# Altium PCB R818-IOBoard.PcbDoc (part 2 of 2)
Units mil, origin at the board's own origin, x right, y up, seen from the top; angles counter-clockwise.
Board outline 4330.71 x 4330.71 mil, 4 copper layers (Top Layer, Layer 2, Layer 1, Bottom Layer), stack 33.574 mil thick; 161 components, 167 nets, 792 pads, 698 vias.
Unrouted connection lines stored in the file: 71.
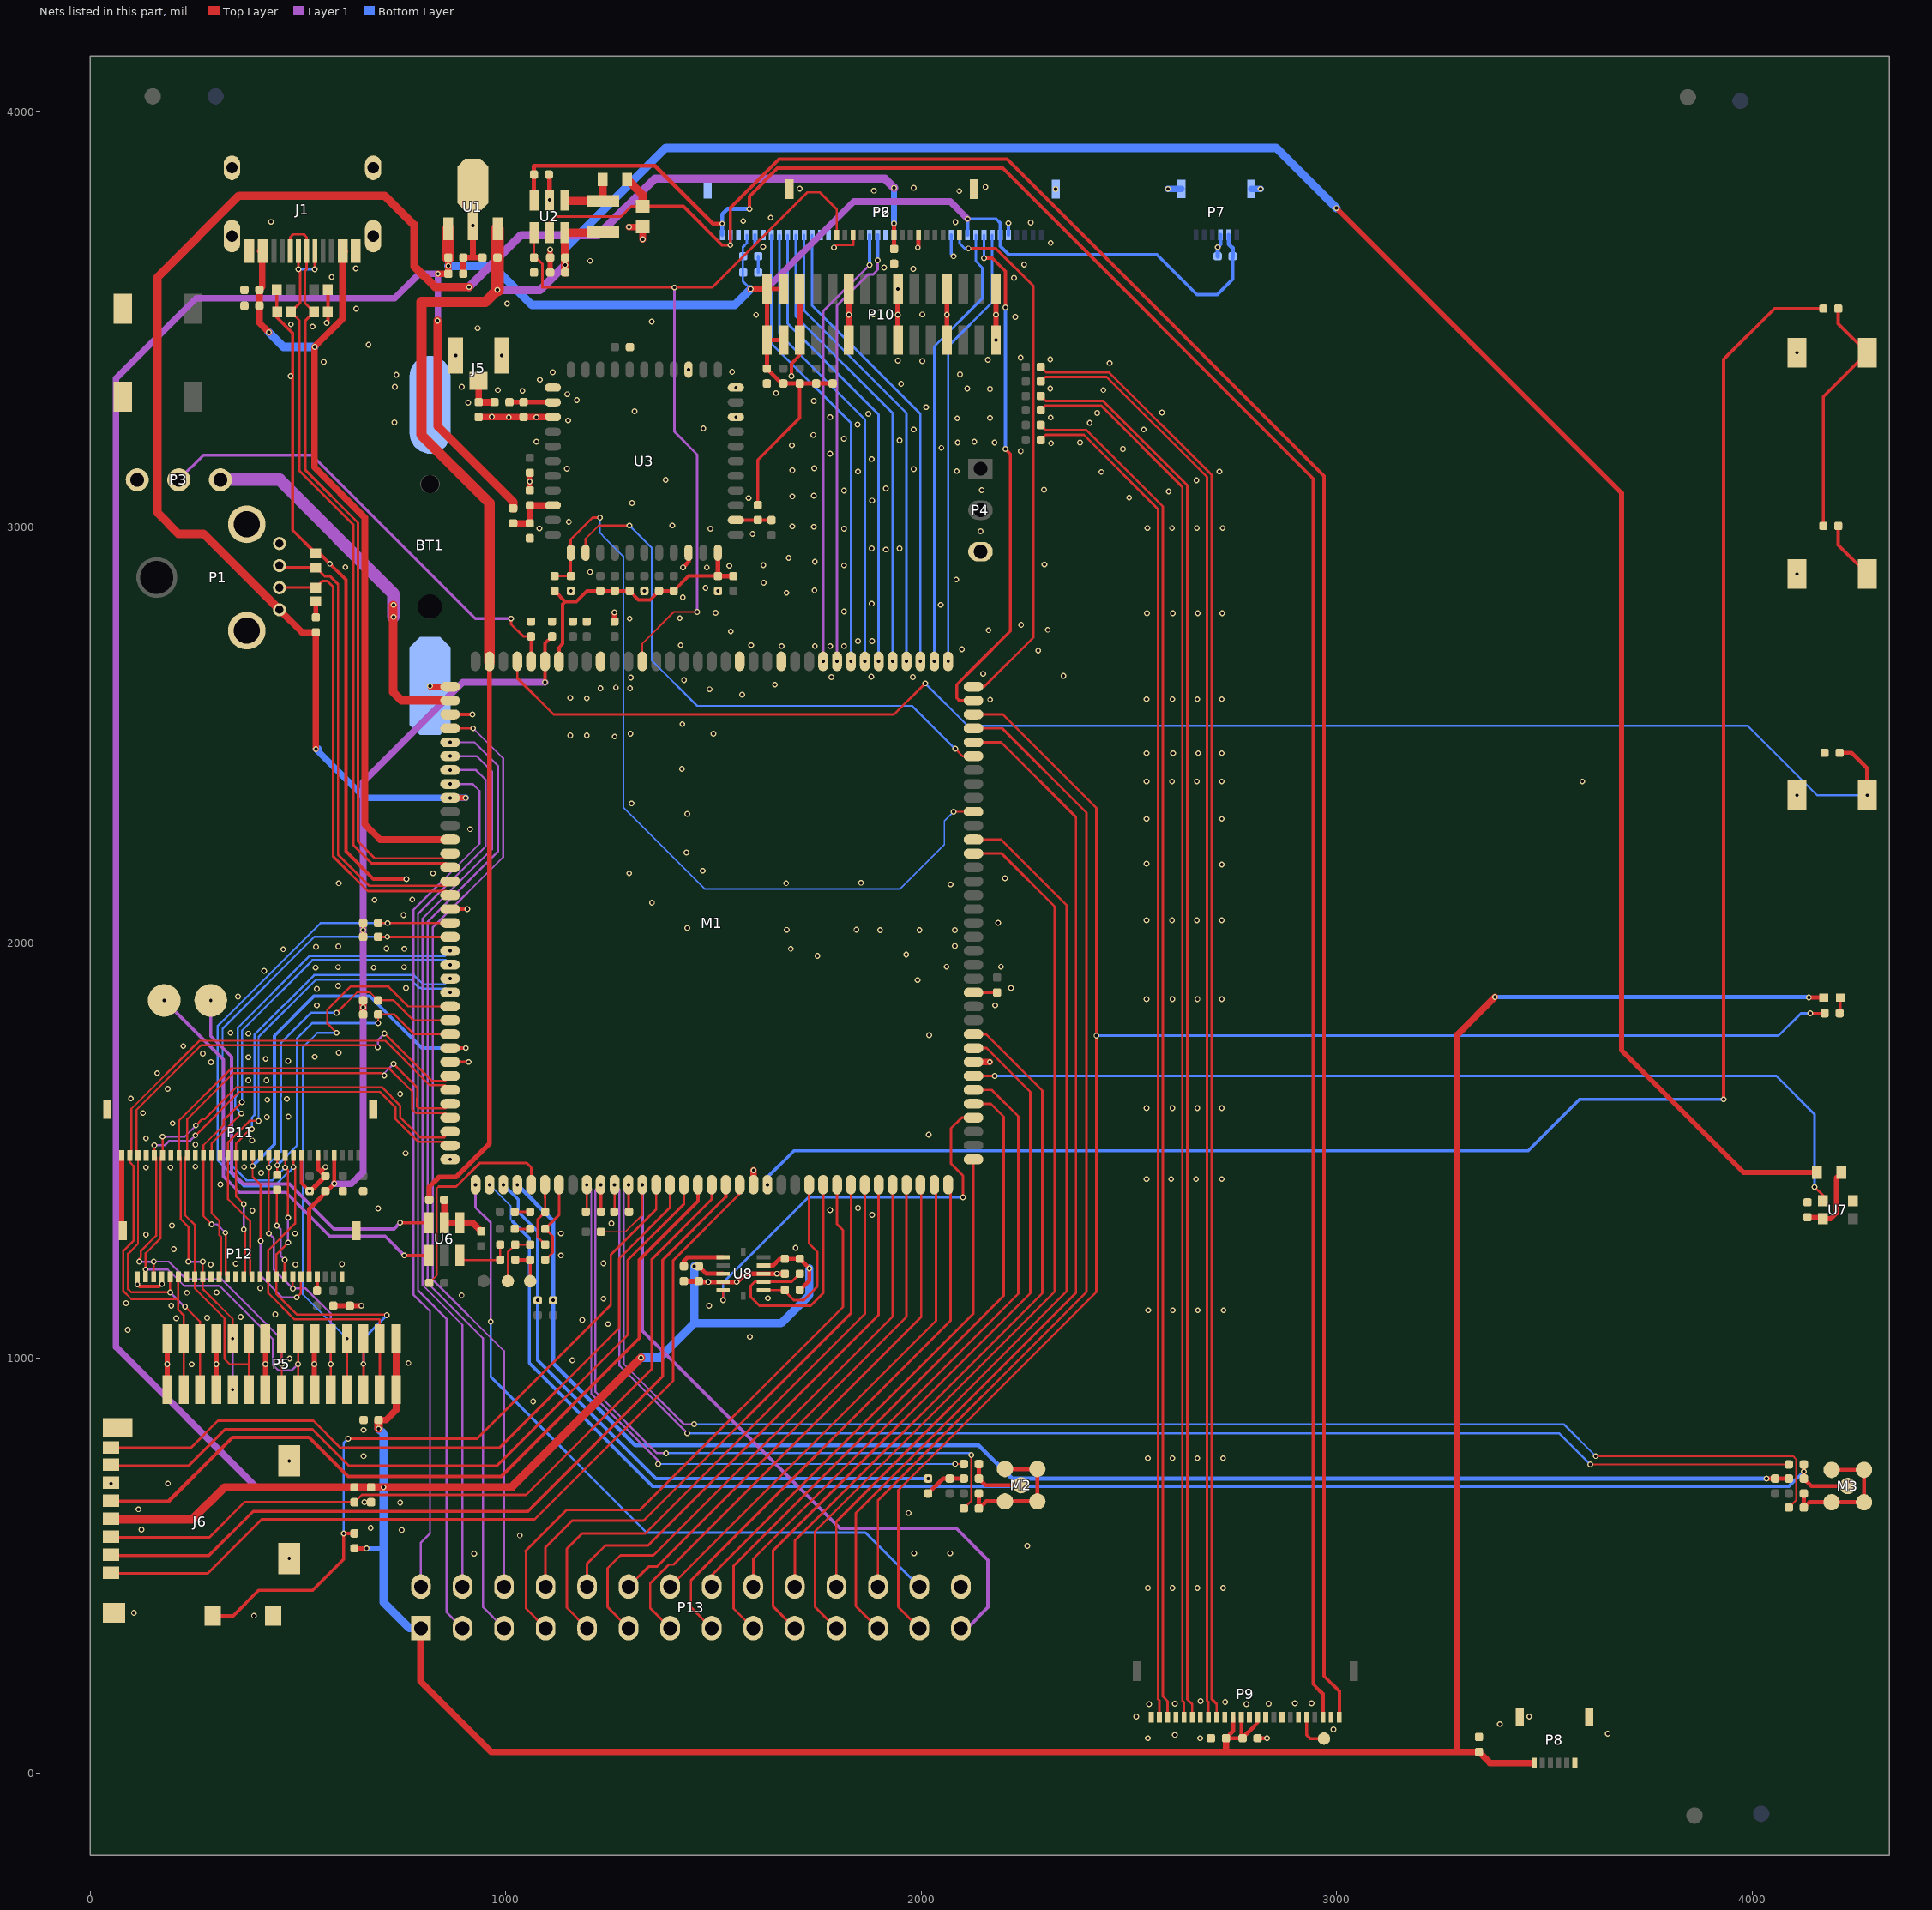
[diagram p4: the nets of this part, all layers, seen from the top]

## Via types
v1: diameter 14, hole 8, Top Layer to Bottom Layer, tented both sides, 698 vias

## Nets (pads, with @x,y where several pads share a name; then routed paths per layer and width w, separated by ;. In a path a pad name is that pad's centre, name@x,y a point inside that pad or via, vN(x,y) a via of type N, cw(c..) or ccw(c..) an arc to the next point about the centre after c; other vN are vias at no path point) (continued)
GND: BT1.2 C1.1 C2.1 C3.1 C4.1 C5.1 C6.1 C9.2 C10.2 C11.1 C12.2 C13.2 C14.1 C15.2 C16.2 C17.2 C18.2 C19.2 C20.1 C21.2 C22.2 C23.2 C24.2 C25.1 C26.1 C27.2 C28.2 C29.2 C30.2 C31.2 C32.2 C35.1 C36.1 C37.2 C45.2 C47.1 C48.1 C49.1 C50.1 C54.2 D2.1 D3.1 D4.1 D5.1 D6.1 D7.1 J1.0 J1.A1 J1.A12 J1.B1 J1.B12 J5.2 J5.3 J6.6 J6.G1 J6.G2 J6.G3 J6.G4 J6.G5 M1.21 M1.43 M1.83 M1.86 M1.96 M1.108 M1.122 M1.133 M1.140 P1.4 P1.5 P1.6 P2.1 P2.6 P2.14 P2.G P3.3 P4.3 P5.1 P5.4 P5.7 P5.10 P6.3 P6.5 P6.6 P6.13 P6.14 P6.21 P6.22 P6.29 P6.36 P6.G P7.3 P7.G P8.1 P8.G P9.2 P9.6 P9.8 P9.10 P9.12 P9.15 P9.18 P9.21 P9.24 P10.1 P10.4 P10.7 P10.10 P10.13 P11.6 P11.8 P11.13 P11.15 P11.18 P11.21 P11.24 P11.27 P11.30 P11.G P12.1 P12.11 P12.14 P12.17 P12.20 P12.23 P12.26 P12.G P13.28 R1.1 R2.1 R4.1 R14.2 R19.1 R26.1 R47.1 S1.2 S2.1 S4.1 S5.1 S6.1 U1.2 U2.2 U3.1 U3.3 U3.20 U3.31 U3.33 U3.36 U7.2 U8.4 U8.8 | length 4980.9
  Top Layer w6: v1(1789.7,3673) 1795.7,3679 1836.08,3679 P2.14@1836.08,3703.31
  Top Layer w7.87: v1(1687.7,3364) 1687.7,3394 1707.63,3413.93 P10.13@1707.63,3450.17
  Top Layer w8: P12.26@113.15,1195.68 v1(113.15,1177.55) 118.7,1172 165.7,1172 v1(172.2,1178.5) P12.23@172.2,1195.68 ; D5.1@448.7,3572 448.7,3505 486.7,3467 486.7,2992.73 D6.1@542.7,2936.73 551.97,2936.73 v1(576.7,2912) 615.04,2873.66 615.04,2219.66 681.7,2153 v1(760.7,2153) ; P11.8@508.34,1487.68 508.34,1421.36 v1(527.7,1402) ; v1(568.7,3492) 571.7,3495 D3.1@571.7,3518 D2.1@571.7,3572 ; v1(659.7,653) C24.2@675.7,653 ; M1.133@866.14,1712.6 v1(910.3,1712.6) ; M1.122@866.14,2080.71 v1(907.41,2080.71) ; M1.108@866.14,2549.21 v1(919.91,2549.21)
  Top Layer w10: 553.2,1450.5 556.2,1450.5 v1(565.7,1460) ; v1(1426.7,2903) 1439.86,2916.16 U3.20@1439.86,2938.43 ; v1(1991.7,3673) 1993.56,3674.86 P2.6@1993.56,3703.31 ; C22.2@2809.7,85 v1(2832.7,85)
  Top Layer w11.81: v1(2180.07,3450.17) P10.1@2180.07,3573
  Top Layer w12: P11.30@75.27,1487.68 75.27,1309.35 P12.G@78.3,1306.32 ; P5.1@184.85,924.17 P5.1@184.85,1047 ; P5.4@302.96,924.17 P5.4@302.96,1047 ; P5.7@421.07,924.17 P5.7@421.07,1047 ; v1(527.7,1402) 529.7,1402 C47.1@565.7,1438 553.2,1450.5 547.71,1455.99 P11.6@547.71,1487.68 ; P5.10@539.18,924.17 P5.10@539.18,1047 ; C18.2@542.7,2783 D7.1@542.7,2821.27 ; C29.2@584.7,1126 C30.2@624.7,1126 v1(652.7,1126) ; C4.1@1057.69,3088.37 R14.2@1057.69,3131 ; R1.1@1103.7,3849 1105.11,3847.59 v1(1105.11,3787.63) ; C10.2@1106.7,3613 C11.1@1106.7,3649 v1(1106.7,3668) ; M1.96@1225.7,2678.03 M1.96@1228.35,2675.39 ; C25.1@1261.7,2773 v1(1261.7,2795) ; R47.1@1428.7,1185 C36.1@1464.7,1185 1466.39,1183.31 U8.4@1523.06,1183.31 v1(1556.01,1183.31) v1(1575.7,1203) U8.8@1620.7,1203 C35.1@1671.7,1203 ; P10.7@1943.85,3450.17 v1(1943.85,3573) ; P10.4@2061.96,3450.17 P10.4@2061.96,3573
  Top Layer w14: C32.2@897.7,3610 C16.2@897.7,3649 920.7,3649 ; v1(920.7,3726.01) 920.7,3649 ; C19.2@943.7,3649 920.7,3649
  Top Layer w15.75: v1(1296.4,3722.7) C12.2@1329.7,3722.7 v1(1329.7,3693) ; P10.13@1707.63,3450.17 P10.13@1707.63,3573 ; P10.10@1825.74,3450.17 P10.10@1825.74,3573
  Top Layer w16: S4.1@76.28,3314.08 S4.1@76.7,3314.5 ; C1.1@934.7,3265 934.9,3265.2 U3.3@1113.09,3265.2 ; M1.21@1596.45,1417.32 v1(1596.45,1452.25) ; M1.43@2125.98,1712.6 v1(2165.1,1712.6)
  Bottom Layer w7.87: 1599.86,3680.84 P6.5@1599.86,3703.31 ; C14.1@1607.7,3613 C9.2@1607.7,3652 ; P6.36@2210.1,3703.31 v1(2210.1,3731.6)
  Bottom Layer w8: P6.29@2072.3,3703.31 2072.3,3657.4 v1(2077.7,3652)
  Bottom Layer w10: C13.2@2713.7,3652 v1(2713.7,3674) 2720.54,3680.84 P7.3@2720.54,3703.68
  Bottom Layer w16: v1(2594.02,3814.32) P7.G@2626.64,3814.32 ; P7.G@2794.76,3814.32 v1(2817.02,3814.32)
  other v1: 2545.7,85 2671.7,85 2610.7,93 3652.7,96 2992.7,106 3392.7,119 2517.7,137 3463.7,137 2548.7,167 2782.7,167 2610.7,168 2836.7,168 2899.7,169 2939.7,169 2731.7,172 2672.7,174 393.7,380 104.7,387 2545.7,447 2604.7,447 2664.7,447 2726.7,447 478.56,517.57 923.7,529 1982.7,530 2069.7,530 2255.64,547.67 1033.7,573 749.7,586 122.7,587 674.7,591 1969.7,627 115.7,636 745.7,652 50,698.08 186.62,698.08 478.56,752.61 2545.7,759 2604.7,759 2664.7,759 2726.7,759 657.7,764 657.7,827 1065.7,896 243.7,985 184.85,985.58 302.96,985.58 421.07,985.58 539.18,985.58 765.7,988 1160,995 479.7,999 1587.7,1051 89.72,1068.31 1246,1082 1184,1092 206.7,1096 280.7,1097 361.7,1099 445,1105 2546.7,1115 2605.7,1115 2665.7,1115 2727.7,1115 194.7,1126 1489.7,1126 85.7,1132 1235,1143 1630.94,1143.94 893.7,1151 232.04,1157.18 303.7,1158 408.7,1168 1487.7,1183 1652.7,1203 289.7,1225 493.7,1225 605.7,1226 349.7,1227 1235,1228 1132.7,1247 200.7,1262 1697.7,1265 133.7,1297 492.7,1300 1132.7,1300 196,1319 1254,1324 1881.7,1345 389.7,1355 1780.7,1356 692.7,1360 1847.7,1361 312.7,1418 2542.7,1431 2601.7,1431 2661.7,1431 2723.7,1431 410.7,1446 133.7,1459 192.7,1459 370,1460 252.7,1461 866.14,1478.35 758.7,1493 252.7,1514 389,1524 133.7,1529 2018,1538 197.7,1565 424.7,1580 476.7,1581 126.7,1590 2542.7,1602 2604.7,1602 2664.7,1602 2723.7,1602 425.7,1622 472.7,1624 97.7,1625 745.7,1636 185.7,1648 379.7,1669 423.7,1669 160.7,1686 290.37,1712.34 475.7,1715 421.7,1720 380,1724 540,1725 270.7,1733 597.7,1735 223.7,1751 2019,1777 379.7,1781 337,1783 545,1849 2178,1849 2542.7,1864.17 2604.89,1864.17 2664.89,1864.17 2723.7,1864.17 355,1870 545,1889 760,1891 2216,1891 596,1896 1991,1910 418,1932 542,1940 682,1940 596,1941 755,1941 2061,1942 2192,1942 1750,1968 1964,1971 464,1984 755.7,1985 1686,1985 712.7,1986 543,1990 597,1991 2081,1992 1901,2030 1996,2030 2081,2030 1676.64,2030.8 1844,2031 1436.77,2035.33 2185.11,2047.9 2542.7,2054 2603.7,2054 2663.7,2054 2723.7,2054 754,2066 1352,2096 684,2103 775,2104 2071,2140 598,2143 1675,2143 1855,2144 2202,2155 825,2167 1297,2167 1474,2173 2723.7,2188 2542.7,2190 1435,2217 914,2273 2542.7,2298 2723.7,2298 1437,2310 1303,2335 4108.4,2354.72 2542.7,2388 2603.7,2388 2663.7,2388 2723.7,2388 3591.71,2388 1424,2418 2542.7,2456 2606.7,2456 2666.7,2456 2723.7,2456 1262,2496 1155,2499 1195,2499 1300,2503 1500,2503 1425,2526 2166,2585 2542.7,2586 2604.7,2586 2664.7,2586 2723.7,2586 1195,2588 1155,2589 1569,2597 1490.63,2609.86 1228,2612 1299,2612 1265,2614 1648,2621 1429,2632 1301,2638 1784,2639 1980,2639 1880,2640 2342.7,2642 2149,2647 2281.7,2703 2098,2706 1664,2714 1744,2714 1781,2714 1814,2714 1421,2716 1591,2716 1848,2726 1882,2726 1541.7,2749 2162,2752 2304.7,2753 2240.7,2765 1298,2780 1419,2781 2543.7,2793 2605.7,2793 2665.7,2793 2724.7,2793 1505,2794 1814,2797 2047,2813 1881,2816 1426,2831 1676,2842 1156.69,2846.37 1333.57,2846.37 1510.69,2846.37 1743,2848 1481,2854 1621,2866 2084.47,2873.92 4108.4,2887.36 1203,2892 1484,2903 613.7,2904 1538,2907 1814,2908 1620.17,2908.4 2296.7,2910 1744,2917 1681,2926 1914.7,2946 1880.7,2949 1947.7,2949 1594.17,2984.16 2142.7,2990 1492.7,2996 1814,2996 1081,2997 2544.7,2998 2603.7,2998 2663.7,2998 2725.7,2998 1741.7,3001 1689.7,3002 1400.7,3004 1151.7,3013 1303.7,3058 1882,3064 1584.7,3070 2500.7,3071 1689.7,3074 1741.7,3076 2595.7,3086 1814,3088 2145.7,3089 2295.7,3090 1915,3093 1057.69,3110 2662.7,3113 1384.7,3114 2433.7,3133 1848,3134 2717.7,3134 2085.7,3135 1689.7,3137 1981.7,3140 1146.7,3141 1742.7,3142 1881,3164 1780.7,3177 2239.7,3183 2485.7,3188 2048.7,3191 1688.7,3197 2312.7,3202 2087.7,3204 2176.7,3204 2382.7,3204 1073.7,3206 2128,3206 1947.7,3209 1813.7,3213 1740.7,3222 1981.7,3235 2535.7,3235 1475.7,3238 1846.7,3247 2405.7,3251 731.7,3252 1150,3257 2086.7,3262 2165.7,3263 2311.7,3264 1007,3265 1073.7,3265 1554.03,3265.2 1780.7,3265 966,3266 1872.7,3273 2423.7,3275 2579.7,3276 1309.7,3279 2011.7,3289 909.65,3299.59 1741.7,3304 1171.25,3305.78 1148,3320 1650.7,3323 1040,3328 981,3330 2438.7,3330 2165.7,3333 2110.7,3334 2310.7,3334 1554.03,3336.06 732.7,3338 894,3338 1951.7,3345 1082,3355 481.7,3364 736.7,3367 2093.7,3368 1112.7,3373 1545,3374 1439.86,3379.37 2453.7,3395 561.7,3398 2002.7,3400 1943.7,3401 2160.7,3403 2310.7,3404 2239.48,3408.07 879.58,3413.02 989.82,3413.02 4108.4,3420 669.7,3439 932,3479 534.7,3483 482.7,3488 1351,3495 2226.7,3506 1602.7,3511 1825.74,3511.58 1884.7,3512 1943.85,3511.58 2002.7,3512 2061.96,3511.58 2180.07,3511.58 639.7,3526 1003,3538 2223.7,3600 580.7,3602 1980.7,3622 638.7,3623 1910.7,3625 2247.7,3632 1203,3641 1619.7,3675 2311.7,3684 2263.7,3733 2082.7,3734 434.7,3735 1571.74,3736.8 1637.7,3745 1893.7,3760 2091.7,3809 1885.7,3810 2323.68,3813.95 1707.7,3815 1982,3817 2154.7,3819
GS-INT: M1.39 U8.5 | length 972
  Top Layer w6: v1(1523.06,1139.36) U8.5@1523.06,1163.63 ; v1(2100.7,1387) 2100.7,1439 2071.7,1468 2071.7,1553 2097.44,1578.74 M1.39@2125.98,1578.74
  Bottom Layer w6: v1(1523.06,1139.36) 1523.06,1181.36 1728.7,1387 v1(2100.7,1387)
HBIAS: C44.2 C51.2 M1.4 R54.1 | length 3555.2
  Top Layer w10: v1(4034.7,710) C44.2@4055.7,710 R54.1@4088.7,710
  Bottom Layer w10: v1(1027.56,1417.32) 1113.7,1331.18 v1(1113.7,1139) 1113.7,988 1311.7,790 2138.7,790 2218.7,710 v1(4034.7,710)
HP-DET: M1.13 P13.27 R27.2 | length 1801.9
  Top Layer w4: R27.2@1228,1304 1288,1304 1328.74,1344.74 v1(1328.74,1417.32)
  Layer 1 w8: v1(1328.74,1417.32) 1328.74,1065.96 1804.7,590 2084.7,590 2160.7,514 2160.7,400 2110.7,350 P13.27@2095.7,350
HPOUTFB: M1.5 R33.2 | length 533.5
  Top Layer w4: R33.2@815.7,1181 833.7,1199 833.7,1408 838.7,1413
  Top Layer w6: 838.7,1413 880.7,1413 937.7,1470 1049.7,1470 1061.02,1458.68 M1.5@1061.02,1417.32
HS-MIC: C40.1 M1.2 M3.1 R54.2 | length 3822.5
  Top Layer w10: C40.1@4124.7,744 v1(4124.7,727) R54.2@4124.7,710 4142.7,692 M3.1@4230.7,692
  Bottom Layer w4: v1(960.63,1417.32) 1011.7,1366.25 1011.7,1333 1016.7,1328
  Bottom Layer w8: 1016.7,1328 1056.7,1288 1056.7,988 1353.7,691 4088.7,691 v1(4124.7,727)
IOVDD_CSI: C47.2 C50.2 M1.100 P11.4 P12.5 R48.2 R49.2 R50.2 R51.1 | length 2061.2
  Top Layer w8: v1(1094.49,2626.79) M1.100@1094.49,2677.17 ; M1.100@1094.49,2675.39 1094.49,2720.29 C50.2@1111.2,2737
  Top Layer w10: P12.5@526.53,1195.68 526.53,1358.83 587.08,1419.38 v1(587.08,1420) P11.4@587.08,1487.68 ; R50.2@656.7,2014 v1(656.7,2030.5) R51.1@656.7,2047
  Top Layer w16: R48.2@656.7,1827 v1(656.7,1844) R49.2@656.7,1861
  Layer 1 w16: v1(587.08,1420) 587.08,1419.38 628.08,1419.38 656.7,1448 v1(656.7,1844) v1(656.7,2030.5) 656.7,2387 896.49,2626.79 v1(1094.49,2626.79)
LCD_CLK: M1.70 P6.30 | length 1279.4
  Top Layer w6: v1(2113.7,3671) 2179.7,3671 2269.7,3581 2269.7,2734 2151.84,2616.14 M1.70@2125.98,2616.14
  Bottom Layer w6: P6.30@2091.99,3703.31 2091.99,3683.71 2104.7,3671 v1(2113.7,3671)
LCD_D14: M1.80 P6.19 | length 1072.7
  Layer 1 w6: v1(1763.78,2677.17) 1763.78,3519.57 1875.33,3631.12 v1(1875.45,3631)
  Bottom Layer w7.87: v1(1875.45,3631) P6.19@1875.45,3703.31
LCD_D15: M1.79 P6.20 | length 1073.7
  Layer 1 w6: v1(1797.24,2677.17) 1797.24,3533.54 1871.7,3608 1883.7,3608 1895.14,3619.44 v1(1895.14,3642.44)
  Bottom Layer w7.87: v1(1895.14,3642.44) P6.20@1895.14,3703.31
LCD_D18: M1.78 P6.7 | length 1105.5
  Bottom Layer w6: P6.7@1639.23,3703.31 1639.23,3442.47 1830.71,3250.99 v1(1830.71,2677.17)
LCD_D19: M1.77 P6.8 | length 1111.2
  Bottom Layer w6: P6.8@1658.92,3703.31 1658.92,3464.78 1864.17,3259.53 v1(1864.17,2677.17)
LCD_D20: M1.76 P6.9 | length 1116.9
  Bottom Layer w6: P6.9@1678.6,3703.31 1678.6,3490.1 1897.64,3271.06 v1(1897.64,2677.17)
LCD_D21: M1.75 P6.10 | length 1122.6
  Bottom Layer w6: P6.10@1698.29,3703.31 1698.29,3507.41 1931.1,3274.6 v1(1931.1,2677.17)
LCD_D22: M1.74 P6.11 | length 1128.3
  Bottom Layer w6: P6.11@1717.97,3703.31 1717.97,3521.73 1964.56,3275.14 v1(1964.56,2677.17)
LCD_D23: M1.73 P6.12 | length 1134
  Bottom Layer w6: P6.12@1737.66,3703.31 1737.66,3533.04 1998.03,3272.67 v1(1998.03,2677.17)
LCD_DE: M1.71 P6.34 | length 1070
  Bottom Layer w6: v1(2064.96,2677.17) 2064.96,3435.26 2170.73,3541.03 P6.34@2170.73,3703.31
LCD_HSYNC: M1.72 P6.32 | length 1080.2
  Bottom Layer w6: v1(2031.49,2677.17) 2031.49,3434.79 2146.7,3550 2146.7,3625 2131.36,3640.34 P6.32@2131.36,3703.31
LCD_PWM: M1.93 P2.16 R2.2 U2.4 | length 2036.9
  Top Layer w4: M1.93@1328.74,2677.17 1328.74,2720.04 1404.7,2796 v1(1460.7,2796)
  Top Layer w6: U2.4@1067.71,3708.89 R2.2@1067.7,3649 1072.7,3649 1087.7,3634 1087.7,3576.96 v1(1405.7,3576.96) 1496.66,3576.96 1725.7,3806 1756,3806 1796.71,3765.29 P2.16@1796.71,3703.31
  Layer 1 w6: v1@1405.7,3578 1405.7,3230 1460.7,3175 v1(1460.7,2796)
LCD_VSYNC: M1.69 P6.33 | length 1248.9
  Top Layer w8: M1.69@2125.98,2582.67 2092.03,2582.67 2085.7,2589 2085.7,2621 2129.7,2665 2214.7,2750 2214.7,3176 v1(2202.7,3188) ; v1(2151.04,3647.34) 2171.36,3647.34 2202.7,3616 v1(2202.7,3529)
  Bottom Layer w6: v1(2151.04,3647.34) P6.33@2151.04,3703.31
  Bottom Layer w8: v1(2202.7,3188) v1(2202.7,3529)
LEDA: C12.1 D1.K P6.2 P9.1 U2.5 | length 5505.5
  Top Layer w6: U2.5@1105.11,3708.89 1105.11,3733.41 1119.7,3748 1277.31,3748 1302.01,3772.7 C12.1@1329.7,3772.7
  Top Layer w8: C12.1@1329.7,3772.7 1427.3,3772.7 1520.89,3679.11 v1(1540.81,3679.11) 1540.81,3769.11 1657.7,3886 2207,3886 2970,3123 2970,234.7 3006.61,198.1 P9.1@3006.61,135.63
  Top Layer w20: D1.K@1292.23,3837 1329.7,3799.53 C12.1@1329.7,3772.7
  Bottom Layer w8: v1(1540.81,3679.11) P6.2@1540.81,3703.31
LEDK: P6.1 P9.3 R1.2 U2.3 | length 5430.3
  Top Layer w8: v1(1586.63,3765.93) 1586.63,3796.54 1654.09,3864 2196.32,3864 2943.7,3116.62 2943.7,215 2959.35,199.35
  Top Layer w10: U2.3@1067.71,3787.63 R1.2@1067.7,3849 1067.7,3870 1359,3870 1498.42,3730.58 v1(1521.12,3730.58) ; 2959.35,199.35 2967.24,191.47 P9.3@2967.24,135.63
  Bottom Layer w10: P6.1@1521.12,3703.31 v1(1521.12,3730.58) 1521.12,3753.42 1533.7,3766 1586.56,3766 v1(1586.63,3765.93)
LO: C7.1 C33.1 M1.6 | length 159.3
  Top Layer w6: M1.6@1094.49,1417.32 1094.49,1384.79 1094.7,1384.57 C33.1@1094.7,1352 1076.7,1334 1076.7,1291 C7.1@1094.7,1273
LRADC: M1.22 R36.1 | length 4468.8
  Top Layer w8: v1(3931.7,1623) 3931.7,3403.7 4054,3526 R36.1@4171.7,3526
  Bottom Layer w8: v1(1629.92,1417.32) 1629.92,1435.22 1693.7,1499 3460.7,1499 3584.7,1623 v1(3931.7,1623)
MBIAS: C46.2 M1.3 R52.1 | length 1514.6
  Bottom Layer w8: v1(994.09,1417.32) 1029.7,1381.72 1029.7,1352 1076.7,1305 v1(1076.7,1139) 1076.7,995 1361.7,710 v1(2016.7,710)
MCSI_MCLK: M1.132 P11.14 P12.6 | length 1385.4
  Top Layer w5: P11.14@390.23,1487.68 v1(390.23,1462.08) 390.23,1436.47 409.7,1417 v1(409.7,1282) ; v1(496.7,1146) 506.85,1156.15 P12.6@506.85,1195.68
  Top Layer w8: M1.132@866.14,1746.06 v1(903.76,1746.06)
  Layer 1 w5: v1(409.7,1282) 409.7,1198 461.7,1146 v1(496.7,1146)
  Bottom Layer w8: v1(390.23,1462.08) 442.7,1514.55 442.7,1775.7 538,1871 672.7,1871 797.64,1746.06 v1(903.76,1746.06)
MCSI_SCL: M1.124 P5.13 P11.10 P12.9 R50.1 | length 2055
  Top Layer w5: P11.10@468.97,1487.68 v1(468.97,1458.73) 475.7,1452 v1(475.7,1338) ; v1(475.7,1278) 447.79,1250.09 P12.9@447.79,1195.68 447.79,1153.91 496.7,1105 711.7,1105 v1(713.7,1103)
  Top Layer w6: P5.13@657.29,924.17 v1(657.29,986) P5.13@657.29,1047 ; R50.1@692.7,2014 692.8,2014.1 694.69,2013.99 865.93,2013.99 M1.124@866.14,2013.78
  Layer 1 w5: v1(475.7,1278) v1(475.7,1338)
  Bottom Layer w5: v1(468.97,1458.73) 438.24,1428 375.7,1428 318,1485.7 318,1793 539,2014 696.7,2014 v1(714.7,2014)
  Bottom Layer w6: v1(657.29,986) 657.29,1046.59 v1(713.7,1103)
MCSI_SDA: M1.123 P5.14 P11.9 P12.10 R51.2 | length 2059.2
  Top Layer w5: v1@488.65,1460 P11.9@488.65,1487.68 ; v1(488.7,1460) 492.7,1456 492.7,1324 428.11,1259.41 P12.10@428.11,1195.68 428.11,1156.59 491.7,1093 696.66,1093 P5.14@696.66,1047
  Top Layer w6: R51.2@694.7,2047 694.94,2047.24 M1.123@866.14,2047.24 ; P5.14@696.66,924.17 P5.14@696.66,1047
  Bottom Layer w5: v1(488.7,1460) 483.47,1454.77 483.47,1452.73 474.97,1444.23 472.93,1444.23 441.7,1413 369.7,1413 306,1476.7 306,1799 320.7,1813.7 554,2047 v1(715.7,2047)
MCSIA-CLKN: M1.139 P5.8 P11.26 P12.24 | length 1773.6
  Top Layer w5: v1(117.7,1232) 117.7,1239 121.7,1243 121.7,1258 158.7,1295 158.7,1482.99 P11.26@154.01,1487.68 v1(154.01,1512.31) ; P12.24@152.52,1195.68 v1(152.52,1232.18) ; v1(252.7,1536) 357.7,1641 696.7,1641 734.7,1603 734.7,1575 788.7,1521 856.95,1521 M1.139@866.14,1511.81 ; P5.8@460.44,924.17 v1(460.44,985.58) P5.8@460.44,1047
  Layer 1 w5: v1(117.7,1232) 152.33,1232 v1(152.52,1232.18) 188.52,1232.18 231.7,1189 316.36,1189 460.44,1044.92 v1(460.44,985.58) ; v1(154.01,1512.31) 179.01,1512.31 189.69,1522.99 239.69,1522.99 v1(252.7,1536)
MCSIA-CLKP: M1.138 P5.9 P11.25 P12.25 | length 1800.9
  Top Layer w5: P12.25@132.83,1195.68 v1(132.83,1213.17) 132.83,1252.13 168.7,1288 168.7,1482.69 P11.25@173.69,1487.68 v1(173.69,1532.99) ; v1(253.7,1560) 268.7,1575 274.7,1575 351.7,1652 701.7,1652 745.7,1608 745.7,1580 794.7,1531 851.87,1531 M1.138@866.14,1545.28 ; P5.9@499.81,924.17 v1(499.81,985.58) P5.9@499.81,1047
  Layer 1 w5: v1(132.83,1213.17) 186.53,1213.17 225.7,1174 310.7,1174 439.7,1045 439.7,983 451.7,971 485.23,971 v1(499.81,985.58) ; v1(173.69,1532.99) 226.69,1532.99 v1(253.7,1560)
MCSIA-D0N: M1.135 P5.2 P11.29 P12.21 | length 1757
  Top Layer w5: P12.21@211.57,1195.68 211.57,1145 ; P5.2@224.22,924.17 P5.2@224.22,1047 224.22,1103.48 211.57,1116.13 211.57,1145 ; M1.135@866.14,1645.67 854.81,1657 816.7,1657 709.92,1763.78 262.33,1763.78 98.7,1600.15 98.7,1491.43 P11.29@94.95,1487.68 94.95,1471.75 103.7,1463 103.7,1282 78.7,1257 78.7,1162 98.7,1142 208.57,1142 211.57,1145
MCSIA-D0P: M1.134 P5.3 P11.28 P12.22 | length 1747.5
  Top Layer w5: P12.22@191.89,1195.68 v1(191.89,1158) 98.7,1158 90.7,1166 90.7,1251 114.64,1274.94 P11.28@114.64,1487.68 110.7,1491.62 110.7,1597 266.7,1753 686.9,1753 v1(691.9,1748) ; v1(227.7,1124) 263.59,1088.11 P5.3@263.59,1047 P5.3@263.59,924.17 ; v1@708.48,1781.22 822.7,1667 854.01,1667 M1.134@866.14,1679.13
  Layer 1 w5: v1(191.89,1158) 225.89,1124 v1(227.7,1124) ; v1(691.9,1748) 691.9,1765.2 v1(707.92,1781.22) v1@708.2,1781.5
MCSIA-D1N: M1.137 P5.5 P11.23 P12.18 | length 1517.8
  Top Layer w4: M1.137@866.14,1578.74 M1.137@883.44,1578.74
  Top Layer w5: v1(235.7,1232) 235.7,1316 217.7,1334 217.7,1483.04 P11.23@213.06,1487.68 213.06,1571.36 338.55,1696.85 719.85,1696.85 774.7,1642 774.7,1599 783.7,1590 854.88,1590 M1.137@866.14,1578.74 ; v1(270.7,1232) 270.63,1231.93 P12.18@270.63,1195.68 270.63,1166.07 342.33,1094.37 v1(342.33,1047)
  Layer 1 w5: v1(235.7,1232) v1(270.7,1232) ; v1(342.33,924.17) v1(342.33,1047)
MCSIA-D1P: M1.136 P5.6 P11.22 P12.19 | length 1579.2
  Top Layer w5: P5.6@381.7,924.17 381.7,985.58 ; P5.6@381.7,1047 381.7,985.58 ; v1(707.7,1680) 701.7,1686 343.7,1686 232.75,1575.05 P11.22@232.75,1487.68 227.7,1482.63 227.7,1344 250.94,1320.76 P12.19@250.94,1195.68 250.94,1167.76 322.7,1096 322.7,998 335.12,985.58 381.7,985.58 ; v1(729.7,1708) 786.7,1651 786.7,1627 785.7,1626 785.7,1606 790.7,1601 854.94,1601 M1.136@866.14,1612.2
  Layer 1 w5: v1(707.7,1680) 707.7,1686 v1(729.7,1708)
MCSIA-D2N: M1.126 P11.20 P12.15 | length 1238.6
  Top Layer w5: v1(291.7,1322) 272.12,1341.58 P11.20@272.12,1487.68 272.12,1512.42 316.7,1557 320.2,1560.5 320.2,1571.5 v1(364.7,1616) ; v1(324.7,1302) 325.7,1301 325.7,1199.66 P12.15@329.68,1195.68
  Layer 1 w5: v1(291.7,1322) 304.7,1322 v1(324.7,1302)
  Bottom Layer w5: v1(364.7,1616) 364.7,1788 375.34,1798.64 534.7,1958 854.99,1958 v1(866.14,1946.85)
MCSIA-D2P: M1.125 P11.19 P12.16 | length 1237.4
  Top Layer w5: P12.16@310,1195.68 314.7,1200.39 314.7,1291.49 310.2,1295.99 310.2,1330.5 291.8,1348.9 P11.19@291.8,1487.68 291.8,1517.1 v1(363.7,1589)
  Bottom Layer w5: v1(363.7,1589) 348.7,1604 348.7,1628 354.7,1634 354.7,1795 527.7,1968 853.83,1968 v1(866.14,1980.31)
MCSIA-D3N: M1.128 P11.17 P12.12 | length 1176
  Top Layer w5: P12.12@388.74,1195.68 384.7,1199.72 384.7,1329 331.17,1382.53 P11.17@331.17,1487.68 331.17,1519.46 382.72,1571 v1(404.7,1571)
  Bottom Layer w5: v1(404.7,1571) 404.7,1773 542.7,1911 771.7,1911 791.7,1891 795.56,1891 796.95,1889.61 826.08,1889.61 856.45,1889.61 v1(866.14,1879.92)
MCSIA-D3P: M1.127 P11.16 P12.13 | length 1159.4
  Top Layer w5: P12.13@369.05,1195.68 372.7,1199.33 372.7,1306 v1(369.05,1309.65) ; v1(369.05,1370.65) 350.86,1388.84 P11.16@350.86,1487.68 350.86,1517.1 384.76,1551 v1(388.7,1551)
  Layer 1 w5: v1(369.05,1309.65) v1(369.05,1370.65)
  Bottom Layer w5: v1(388.7,1551) 388.7,1579 394.7,1585 394.7,1778 538.7,1922 778.7,1922 801.09,1899.61 852.37,1899.61 v1(866.14,1913.38)
MCSIA_LED: M1.129 P5.12 | length 1367.8
  Top Layer w5: v1(592.7,1783) 570.7,1805 570.7,1839 625.7,1894 717.7,1894 765.24,1846.46 M1.129@866.14,1846.46 ; P5.12@617.92,924.17 v1(617.92,1047)
  Layer 1 w5: v1(592.7,1783) v1@593.7,1784
  Bottom Layer w5: v1(592.7,1783) 546.7,1783 511.7,1748 511.7,1153.22 v1(617.92,1047)
MCSIA_RST_R: M1.131 P11.11 R8.1 R48.1 | length 797.1
  Top Layer w5: v1(692.7,1806) R48.1@692.7,1827 693.34,1827.64 731.06,1827.64 779.17,1779.53 M1.131@866.14,1779.53
  Top Layer w6: P11.11@449.28,1487.68 449.7,1487.26 v1(449.7,1464.13) R8.1@449.7,1441
  Bottom Layer w6: v1(449.7,1464.13) 497.7,1512.13 497.7,1770 533.7,1806 v1(692.7,1806)
MCSIA_STBY_R: M1.130 P5.11 P11.12 P12.7 R49.1 | length 1531.7
  Top Layer w5: v1(429.6,1299.9) P11.12@429.6,1487.68 ; v1(487.16,1167.46) P12.7@487.16,1195.68 ; P5.11@578.55,924.17 v1(578.55,985.58) P5.11@578.55,1047 ; v1(592.7,1831) 642.7,1881 672.7,1881 R49.1@692.7,1861 692.8,1861.1 729.6,1861.1 777.71,1812.99 M1.130@866.14,1812.99
  Layer 1 w5: v1(429.6,1299.9) 441.7,1287.79 441.7,1212.92 v1(487.16,1167.46) 518.24,1167.46 578.55,1107.15 v1(578.55,985.58)
  Bottom Layer w5: v1(429.7,1459) 429.7,1468.1 458.7,1497.1 458.7,1617.49 458.2,1617.99 458.2,1630.01 458.7,1630.51 458.7,1759 530.7,1831 v1(592.7,1831)
MICIN1N: C43.2 C52.2 M1.10 | length 1673.9
  Top Layer w5: C43.2@2102.7,638 2120.7,656 v1(2120.7,767)
  Top Layer w8: v1(1228.35,1417.32) 1228.7,1416.97 C52.2@1228.7,1352
  Layer 1 w5: v1(1228.35,1417.32) 1215.7,1404.68 1215.7,919 1363.7,771 v1(1385.9,771)
  Bottom Layer w5: v1(1385.9,771) 2116.7,771 v1(2120.7,767)
  Bottom Layer w8: v1(1228.35,1417.32) v1@1228.7,1416.97
MICIN1P: C41.2 C52.1 M1.9 | length 1545.7
  Top Layer w5: C52.1@1192.7,1352 1194.88,1354.18 v1(1194.88,1417.32) ; v1(2081.7,745) C41.2@2102.7,745
  Layer 1 w5: v1(1194.88,1417.32) 1205.7,1406.5 1205.7,914 1366.7,753 v1(1366.7,745)
  Bottom Layer w5: v1(1366.7,745) v1(2081.7,745)
MICIN2N: C42.2 C53.2 M1.12 | length 3543.7
  Top Layer w5: v1(3623.7,764) 4098.7,764 4106.7,756 4106.7,658 C42.2@4088.7,640
  Top Layer w6: v1(1295.27,1417.32) 1295.27,1353.43 C53.2@1296.7,1352
  Layer 1 w5: v1(1295.27,1417.32) 1283.7,1405.75 1283.7,986.14 1428.84,841 v1(1453.7,841)
  Bottom Layer w5: v1(1453.7,841) 3546.7,841 v1(3623.7,764)
MICIN2P: C40.2 C53.1 M1.11 | length 3419.6
  Top Layer w5: C53.1@1260.7,1352 1261.81,1353.11 v1(1261.81,1417.32) ; v1(3610.7,744) C40.2@4088.7,744
  Layer 1 w5: v1(1261.81,1417.32) 1273.7,1405.43 1273.7,982 v1(1436.7,819)
  Bottom Layer w5: v1(1436.7,819) 3535.7,819 v1(3610.7,744)
NetC1_2: C1.2 J5.1 R6.2 | length 89
  Top Layer w16: J5.1@934.7,3352 C1.2@934.7,3301 R6.2@972.7,3301
NetC2_2: C2.2 R6.1 U3.2 | length 104.5
  Top Layer w11.81: R6.1@1008.7,3301 1112.72,3301 U3.2@1113.09,3300.63
NetC7_2: C7.2 R9.2 TP4.1 | length 131.5
  Top Layer w5: TP4.1@1004.7,1185 1004.7,1255 R9.2@1022.7,1273 C7.2@1058.7,1273
NetC8_2: C8.2 R10.2 TP5.1 | length 86
  Top Layer w8: R10.2@1023.7,1236 C8.2@1058.7,1236 TP5.1@1058.7,1185
NetC31_1: C31.1 D8.K U7.4 | length 179.7
  Top Layer w12: C31.1@4133.7,1339 4167.37,1339 U7.4@4171.03,1335.35 4189.35,1335.35 4203,1349 4203,1434.47 D8.K@4215.53,1447
NetC33_2: C33.2 R31.1 | length 37
  Top Layer w6: R31.1@1021.7,1352 C33.2@1058.7,1352
NetC34_2: C34.2 R34.1 | length 37
  Top Layer w6: R34.1@1021.7,1311 C34.2@1058.7,1311
NetC38_1: C38.1 L2.2 U6.4 U6.5 | length 152.6
  Top Layer w15: L2.2@851.7,1381 852.1,1380.6 U6.5@852.1,1325.74 U6.4@889.5,1325.74
  Top Layer w16: U6.4@889.5,1325.74 919.96,1325.74 C38.1@940.7,1305
NetC39_2: C39.2 R52.2 R53.1 | length 100.9
  Top Layer w10: R52.2@2016.7,674 2052.7,710 C39.2@2068.7,710 R53.1@2102.7,710
NetC41_1: C41.1 M2.1 R53.2 | length 143.6
  Top Layer w10: C41.1@2138.7,745 R53.2@2138.7,710 2154.7,694 M2.1@2240.7,694
NetC42_1: C42.1 M3.2 R56.1 | length 340.3
  Top Layer w10: R56.1@4124.7,674 C42.1@4124.7,640 4137.73,653.03 M3.2@4191.73,653.03 M3.2@4269.67,653.03 M3.2@4269.67,730.97 M3.2@4191.73,730.97
NetC43_1: C43.1 M2.2 R55.1 | length 339.9
  Top Layer w10: R55.1@2138.7,674 C43.1@2138.7,638 2155.73,655.03 M2.2@2201.73,655.03 M2.2@2279.67,655.03 M2.2@2279.67,732.97 M2.2@2201.73,732.97
NetD1_A: D1.A L1.2 U2.1 | length 144.4
  Top Layer w20: U2.1@1142.51,3787.63 1145.04,3785.1 L1.2@1233.7,3785.1 1233.17,3785.63 D1.A@1233.17,3837
NetDS1_K: DS1.K R29.2 | length 38.7
  Top Layer w6: R29.2@4211.05,1830 4213.05,1832 DS1.K@4213.05,1867.84
NetM1_48: M1.48 R44.2 | length 56.7
  Top Layer w8: M1.48@2125.98,1879.92 2182.62,1879.92 R44.2@2182.7,1880
NetP9_16: P9.16 R7.2 | length 3514.3
  Top Layer w5.91: R7.2@2287.7,3386 2300.7,3373 2451.7,3373 2698.7,3126 2698.7,180 2711.33,167.37 P9.16@2711.33,135.63
NetP9_17: P9.17 R37.2 | length 3491.4
  Top Layer w5.91: R37.2@2287.7,3351 2298.7,3362 2446.7,3362 2687.7,3121 2687.7,190.95 2687.79,190.85 2687.79,175.48 2691.65,171.63 P9.17@2691.65,135.63
NetP9_19: P9.19 R38.2 | length 3412.2
  Top Layer w5.91: R38.2@2287.7,3316 2299.7,3304 2437.7,3304 2640.7,3101 2640.7,178.42 2652.28,166.85 P9.19@2652.28,135.63
NetP9_20: P9.20 R39.2 | length 3389.7
  Top Layer w5.91: R39.2@2287.7,3282 2298.7,3293 2432.7,3293 2628.7,3097 2628.7,175 2632.59,171.11 P9.20@2632.59,135.63
NetP9_22: P9.22 R40.2 | length 3294.3
  Top Layer w5.91: R40.2@2287.7,3246 2299.7,3234 2397.7,3234 2581.7,3050 2581.7,186 2593.22,174.48 P9.22@2593.22,135.63
NetP9_23: P9.23 R41.2 | length 3270.7
  Top Layer w5.91: R41.2@2287.7,3210 2299.7,3222 2391.7,3222 2569.7,3044 2569.7,180 2573.54,176.16 P9.23@2573.54,135.63
NetP12_4: P12.4 R3.2 | length 33.7
  Top Layer w8: R3.2@546.22,1162 P12.4@546.22,1195.68
NetP12_8: P12.8 R8.2 | length 217.1
  Top Layer w5: v1(448.7,1319) R8.2@448.7,1405 ; P12.8@467.48,1195.68 v1(467.48,1236.22)
  Layer 1 w5: v1(448.7,1319) 458.38,1309.32 458.38,1245.32 v1(467.48,1236.22)
NetR9_1: R9.1 R10.1 U6.3 | length 138.8
  Top Layer w5: U6.3@889.5,1247 900.5,1236 R10.1@986.7,1236 R9.1@986.7,1273
NetR15_1: R15.1 R17.2 U3.24 | length 85.7
  Top Layer w8: U3.24@1554.03,3017.17 R15.1@1606.7,3017.17 1639.53,3017.17 R17.2@1639.7,3017
NetR47_2: R47.2 U8.1 | length 110.8
  Top Layer w10: R47.2@1428.7,1221 1428.7,1234 1437.07,1242.37 U8.1@1523.06,1242.37
NetTP1_1: TP1.1 U6.1 | length 1055.9
  Top Layer w8: v1(755.7,1247) U6.1@814.7,1247
  Layer 1 w8: v1(177.7,1861) 320.2,1718.5 320.2,1437.5 358.7,1399 470.62,1399 576.62,1293 709.7,1293 v1(755.7,1247)
NetTP3_1: TP3.1 U6.6 | length 971.8
  Top Layer w8: v1(745.7,1326) 745.96,1325.74 U6.6@814.7,1325.74
  Layer 1 w8: v1(289.7,1861) 289.7,1775 339.7,1725 339.7,1448 368.7,1419 478.7,1419 586.7,1311 730.7,1311 v1(745.7,1326)
PB2: M1.58 P13.21 | length 2245.7
  Top Layer w6: P13.21@1795.7,350 1744.7,401 1744.7,583 2321.7,1160 2321.7,2087 2194.13,2214.57 M1.58@2125.98,2214.57
PB3: M1.59 P13.22 | length 2160.1
  Top Layer w6: P13.22@1795.7,450 1795.7,606 2350.7,1161 2350.7,2090 2192.67,2248.03 M1.59@2125.98,2248.03
PB4: M1.109 P13.6 | length 2291.8
  Top Layer w5: M1.109@866.14,2515.75 v1(921.45,2515.75)
  Layer 1 w5: v1(921.45,2515.75) 993.7,2443.49 993.7,2206 824.7,2037 824.7,1188 995.7,1017 P13.6@995.7,450
PB5: M1.110 P13.5 | length 2360.9
  Layer 1 w5: v1(866.14,2482.28) 924.42,2482.28 981.7,2425 981.7,2220 811.7,2050 811.7,1181 944.7,1048 944.7,401 P13.5@995.7,350
PB6: M1.111 P13.4 | length 2186.7
  Layer 1 w5: v1(866.14,2448.82) 929.88,2448.82 966.7,2412 966.7,2225 799.7,2058 799.7,1176 895.7,1080 P13.4@895.7,450
PB7: M1.112 P13.3 | length 2249.1
  Layer 1 w5: v1(866.14,2415.35) 928.35,2415.35 951.7,2392 951.7,2232 788.7,2069 788.7,1163 857.7,1094 857.7,388 P13.3@895.7,350
PB8: M1.113 P13.2 | length 2084.1
  Layer 1 w5: P13.2@795.7,450 795.7,556 817.7,578 817.7,1113 777.7,1153 777.7,2079 936.7,2238 936.7,2365 919.81,2381.89 v1(866.14,2381.89)
PE6: M1.1 P13.26 | length 1718.6
  Layer 1 w6: v1(927.17,1417.32) 927.17,1362.54 963.7,1326 v1(963.7,1088)
  Bottom Layer w6: v1(963.7,1088) 963.7,955 1338.7,580 1865.7,580 P13.26@1995.7,450
PH17: M1.40 P13.17 | length 1605.3
  Top Layer w6: P13.17@1595.7,350 1548.7,397 1548.7,500 2198.7,1150 2198.7,1581 2167.5,1612.2 M1.40@2125.98,1612.2
PH18: M1.41 P13.18 | length 1530.4
  Top Layer w6: P13.18@1595.7,450 1595.7,517 2233.7,1155 2233.7,1582 2170.03,1645.67 M1.41@2125.98,1645.67
PH19/LEDC: M1.42 U7.3 | length 2279.6
  Top Layer w6: M1.42@2125.98,1679.13 v1(2176.83,1679.13) ; v1(4150.7,1412) 4171.03,1391.67 U7.3@4171.03,1378.65
  Bottom Layer w6: v1(2176.83,1679.13) 4058.57,1679.13 4150.7,1587 v1(4150.7,1412)
PL9: M1.66 P13.23 | length 2514.9
  Top Layer w6: P13.23@1895.7,350 1842.7,403 1842.7,627 2372.7,1157 2372.7,2302 2192.42,2482.28 M1.66@2125.98,2482.28
PL10: M1.67 P13.24 | length 2426.6
  Top Layer w6: P13.24@1895.7,450 1895.7,657 2397.7,1159 2397.7,2313 2194.95,2515.75 M1.67@2125.98,2515.75
PL11: M1.68 P13.25 R29.1 | length 4357.1
  Top Layer w6: P13.25@1995.7,350 1944.7,401 1944.7,682 2421.7,1159 2421.7,2324 2196.49,2549.21 M1.68@2125.98,2549.21 ; v1(4140,1830) R29.1@4175.05,1830
  Bottom Layer w6: v1(2422,1776) 4064,1776 4118,1830 v1(4140,1830)
PWRON: C54.1 M1.102 S1.1 | length 3616.7
  Top Layer w5.91: M1.102@1027.56,2677.17 1027.56,2636.44 1115,2549 1934.7,2549 v1(2009.7,2624)
  Top Layer w10: C54.1@4210.7,2457 4239.7,2457 4277.7,2419 v1(4277.7,2354.72)
  Bottom Layer w5: v1(2009.7,2624) 2111.7,2522 3989.7,2522 4156.98,2354.72 v1(4277.7,2354.72)
RO: C8.1 C34.1 M1.7 | length 210
  Top Layer w6: C8.1@1094.7,1236 1112.7,1254 1112.7,1293 C34.1@1094.7,1311 1127.95,1344.25 M1.7@1127.95,1417.32
SDC0-CLK: J6.5 M1.17 | length 1940.1
  Top Layer w8: 247.7,715 341.7,809 526.7,809 620.7,715 988.7,715 1321.7,1048 1321.7,1236.7 1462.6,1377.6 M1.17@1462.6,1417.32
  Top Layer w10: J6.5@50,654.77 187.47,654.77 247.7,715
SDC0-CMD: J6.3 M1.18 R28.2 | length 1972.9
  Top Layer w6: J6.3@50,568.16 285.86,568.16 370.7,653 R28.2@635.7,653 653.7,671 1048.7,671 1350.7,973 1350.7,1201 1350.7,1237 1496.06,1382.36 M1.18@1496.06,1417.32
SDC0-D0: J6.7 M1.16 | length 1864
  Top Layer w6: J6.7@50,741.39 237.09,741.39 324.7,829 533.7,829 621.31,741.39 979.09,741.39 1293.71,1056.01 1293.71,1235.71 1429.13,1371.13 M1.16@1429.13,1417.32
SDC0-D1: J6.8 M1.15 | length 1791.2
  Top Layer w6: J6.8@50,784.69 242.39,784.69 306.7,849 536.7,849 601.01,784.69 985.39,784.69 1272.7,1072 1272.7,1239.7 1395.67,1362.67 M1.15@1395.67,1417.32
SDC0-D2: J6.1 M1.20 | length 2083.4
  Top Layer w6: J6.1@50,481.54 282.24,481.54 412.35,611.65 1069.35,611.65 1402.7,945 1402.7,1235 1562.99,1395.29 M1.20@1562.99,1417.32
SDC0-D3: J6.2 M1.19 | length 2030.5
  Top Layer w6: 1377.7,1236 1529.53,1387.83
  Top Layer w7.87: J6.2@50,524.85 285.55,524.85 391.7,631 1052.7,631 1377.7,956 1377.7,1236 ; 1529.53,1387.83 M1.19@1529.53,1417.32
SDC0-DET: J6.G6 M1.14 R30.2 | length 1792.4
  Top Layer w6: v1(620.7,806) 930.7,806 1252.7,1128 1252.7,1248.7 1362.2,1358.2 M1.14@1362.2,1417.32
  Top Layer w7.87: J6.G6@294.51,379.77 343.77,379.77 405,441 535,441 609.7,515.7 v1(609.7,578) R30.2@635.7,578
  Bottom Layer w6: v1(609.7,578) 609.7,795 v1(620.7,806)
SPI2_CLK: M1.32 P13.12 | length 1256.1
  Top Layer w6: P13.12@1295.7,450 1343.7,498 1363.7,498 1964.56,1098.86 M1.32@1964.56,1417.32
SPI2_CS: M1.31 P13.11 | length 1419.6
  Top Layer w6: P13.11@1295.7,350 1244.7,401 1244.7,494 1275.7,525 1355.7,525 1931.1,1100.4 M1.31@1931.1,1417.32
SPI2_MISO: M1.34 P13.14 | length 1232.3
  Top Layer w6: P13.14@1395.7,450 2035.45,1089.75 M1.34@2035.45,1417.32
SPI2_MOSI: M1.33 P13.13 | length 1363.8
  Top Layer w6: P13.13@1395.7,350 1347.7,398 1347.7,458 1392.7,503 1403.7,503 2000.02,1099.32 M1.33@2000.02,1417.32
TE: P9.5 TP2.1 | length 88.3
  Top Layer w8: P9.5@2927.87,135.63 2927.87,92.83 2936.7,84 TP2.1@2969.7,84
TS: M1.101 P3.2 R26.2 | length 1122.3
  Top Layer w6: v1(1012.7,2780) 1012.7,2766.33 1042.03,2737 R26.2@1060.7,2737
  Top Layer w8: M1.101@1060.7,2675.71 R26.2@1060.7,2737
  Layer 1 w7: P3.2@212.7,3114 271.7,3173 533.7,3173 926.7,2780 v1(1012.7,2780)
TWI1_SCL: M1.25 R46.2 U8.6 | length 407.8
  Top Layer w6: U8.6@1620.7,1163.63 R46.2@1671.7,1163.63 1671.7,1161 1693.7,1139 1716.7,1139 1749.7,1172 1749.7,1256 1730.31,1275.39 M1.25@1730.31,1417.32
TWI1_SDA: M1.26 R45.2 U8.7 | length 613.5
  Top Layer w6: R45.2@1707.7,1203 1688.01,1183.31 U8.7@1620.7,1183.31 1599.01,1183.31 1589.7,1174 1589.7,1147 1610.7,1126 1733.7,1126 1763.78,1156.08 M1.26@1763.78,1417.32
TWI3_SCK: M1.35 P13.15 | length 1347
  Top Layer w6: P13.15@1495.7,350 1445.7,400 1445.7,465 2070.89,1090.19 M1.35@2070.89,1417.32
TWI3_SDA: M1.36 P13.16 | length 1289.4
  Top Layer w6: P13.16@1495.7,450 1495.7,477 2125.98,1107.28 M1.36@2125.98,1478.35
UART2_RX: M1.45 P13.20 | length 1662.7
  Top Layer w6: P13.20@1695.7,450 1695.7,560 2291.7,1156 2291.7,1644 2156.17,1779.53 M1.45@2125.98,1779.53
UART2_TX: M1.44 P13.19 | length 1749.2
  Top Layer w6: P13.19@1695.7,350 1643.7,402 1643.7,537 2262.7,1156 2262.7,1641 2157.64,1746.06 M1.44@2125.98,1746.06
UART3_CTS: M1.30 P13.10 | length 1318.4
  Top Layer w6: P13.10@1195.7,450 1195.7,505 1239.7,549 1342.7,549 1897.64,1103.94 M1.30@1897.64,1417.32
UART3_RTS: M1.29 P13.9 | length 1473.8
  Top Layer w6: P13.9@1195.7,350 1146.7,399 1146.7,541 1183.7,578 1335.7,578 1864.17,1106.47 M1.29@1864.17,1417.32
UART3_RX: M1.28 P13.8 | length 1372.5
  Top Layer w6: P13.8@1095.7,450 1095.7,545 1159.7,609 1331.7,609 1830.71,1108.01 M1.28@1830.71,1417.32
UART3_TX: M1.27 P13.7 | length 1513.9
  Top Layer w6: P13.7@1095.7,350 1048.7,397 1048.7,533.34 1046.94,535.1 1146.84,635 1323.7,635 1811.7,1123 1811.7,1308 1797.24,1322.46 M1.27@1797.24,1417.32
USB0_N: D4.2 J1.A7 J1.B7 M1.119 | length 1842.5
  Top Layer w6: J1.A7@500.86,3664.7 v1(500.86,3620.84) 505.25,3616.45 505.25,3540.55 D4.2@482.7,3518 502.7,3498 502.7,3136 632.7,3006 632.7,2235 676.7,2191 856.24,2191 M1.119@866.14,2181.1 ; v1(540.23,3620.47) J1.B7@540.23,3664.7
  Bottom Layer w6: v1(500.86,3620.84) 539.86,3620.84 v1(540.23,3620.47)
USB0_P: D3.2 J1.A6 J1.B6 M1.118 | length 1848.3
  Top Layer w5.91: J1.B6@481.17,3664.7 481.17,3698.47 487.7,3705 513.7,3705 520.54,3698.16 J1.A6@520.54,3664.7 520.54,3620.84 516.7,3617 516.7,3539.54 D3.2@538.24,3518
  Top Layer w6: D3.2@538.24,3518 517.7,3497.46 517.7,3137.26 644.2,3010.76 644.2,2243.5 684.7,2203 854.57,2203 M1.118@866.14,2214.57
USB1_N: D7.2 M1.121 P1.2 | length 1110.9
  Top Layer w6: P1.2@454.98,2854.39 455.31,2854.73 D7.2@542.7,2854.73 557.97,2870 570.7,2870 584.7,2856 584.7,2207 667.7,2124 856.31,2124 M1.121@866.14,2114.17
USB1_P: D6.2 M1.120 P1.3 | length 1115.9
  Top Layer w6: P1.3@454.98,2907.54 459.25,2903.27 D6.2@542.7,2903.27 563.97,2882 576.7,2882 596.2,2862.5 596.2,2211.76 670.96,2137 855.5,2137 M1.120@866.14,2147.64
VBAT: M1.107 P3.1 | length 942.4
  Top Layer w20: v1@728.7,2813 728.7,2603 749.03,2582.67 M1.107@866.14,2582.67
  Layer 1 w30: P3.1@312.7,3114 455.7,3114 729.7,2840 v1(729.7,2813) v1(729.7,2784)
VBUS: C15.1 C17.1 J1.A4 J1.A9 J1.B4 J1.B9 M1.117 | length 2015.8
  Top Layer w15.75: J1.A9@408.34,3664.7 413.7,3659.34 413.7,3578 C17.1@406.7,3571 C15.1@406.7,3533 406.7,3492 v1(429.7,3469) ; J1.A4@613.06,3664.7 606.7,3658.34 606.7,3501 v1(539.7,3434) 539.7,3144 660.7,3023 660.7,2285 697.67,2248.03 M1.117@866.14,2248.03
  Bottom Layer w20: v1(429.7,3469) 464.7,3434 v1(539.7,3434)
VCC3V3: C9.1 C13.1 C14.2 C16.1 C21.1 C22.1 C23.1 C24.1 C26.2 C27.1 C32.1 C35.2 C36.2 DS1.A J6.4 P5.15 P6.4 P6.31 P6.35 P7.2 P8.6 P9.11 P9.13 P9.14 P10.14 P10.15 P13.1 R11.1 R12.1 R13.1 R15.2 R16.2 R25.1 R28.1 R30.1 R45.1 R46.1 U1.1 U8.3 U8.9 | length 17051.6
  Top Layer w7.87: P9.13@2770.39,135.63 2770.39,88.31 C22.1@2773.7,85 ; 2800.65,113.36 2801.87,114.59 2801.87,114.83 2809.76,122.71 P9.11@2809.76,135.63
  Top Layer w8: R15.2@1606.7,3053.17 1606.7,3162 1707.7,3263 R12.1@1707.7,3346
  Top Layer w10: R30.1@635.7,542 v1(664.7,542) ; v1(1453.7,1221) C36.2@1464.7,1221 1482.7,1203 U8.3@1523.06,1203 ; U8.9@1620.7,1222.69 1643.39,1222.69 1659.7,1239 C35.2@1671.7,1239 R45.1@1707.7,1239 v1(1730.7,1216) 1730.7,1186.63 R46.1@1707.7,1163.63 ; P10.14@1668.26,3450.17 P10.15@1628.89,3450.17 ; P10.14@1668.26,3573 P10.15@1628.89,3573 P10.15@1628.89,3450.17 ; R13.1@1786.7,3346 R25.1@1747.2,3346 R12.1@1707.7,3346 R11.1@1668.2,3346 1664.7,3346 C27.1@1628.7,3382 1628.7,3449.98 P10.15@1628.89,3450.17 ; P9.14@2750.7,135.63 2750.7,102 C23.1@2733.7,85 C22.1@2773.7,85 2773.7,86 2801.87,114.17 2801.87,114.59 ; v1(4136.84,1867.84) DS1.A@4173.05,1867.84
  Top Layer w16: C26.2@693.7,851 711.7,851 736.03,875.33 P5.15@736.03,1047 ; P13.1@795.7,350 794.7,349 794.7,222 964.7,52 2733.7,52 ; v1(836.7,3610) C32.1@861.7,3610 861.65,3610.06 861.65,3649 C16.1@861.7,3649 ; v1(1589.7,3573) P10.15@1628.89,3573 ; C23.1@2733.7,85 2733.7,52 ; v1(3381,1869) 3289,1777 3289,52 ; 3467.5,25.31 3369.39,25.31 C21.1@3342.7,52 3289,52 ; 2733.7,52 3289,52
  Top Layer w20: J6.4@50,611.46 245.16,611.46 322.7,689 R28.1@635.7,689 C24.1@675.7,689 v1(705.7,689) 1013.7,689 v1(1325.7,1001) ; v1(693.7,830) C26.2@693.7,851 ; v1(835.7,3496.99) 835.7,3243 1017.7,3061 R16.2@1017.7,3045.37
  Top Layer w30: C16.1@861.65,3649 U1.1@861.65,3718.13
  Layer 1 w16: v1(705.7,689) 399.7,689 61.7,1027 61.7,3358 254.7,3551 732.7,3551 791.7,3610 v1(836.7,3610) 836.7,3497.99 v1(835.7,3496.99) ; v1(1589.7,3573) 1626.7,3573 1837.7,3784 2069.67,3784 v1(2111.67,3742)
  Bottom Layer w6: P6.4@1580.18,3703.31 1580.18,3683.48 1570.7,3674 1570.7,3592 v1(1589.7,3573)
  Bottom Layer w8: P6.31@2111.67,3703.31 v1(2111.67,3742) 2180.7,3742 2190.41,3732.29 P6.35@2190.41,3703.31 2190.41,3676.29 2210.7,3656 2567.7,3656 2663.7,3560 2712.7,3560 2749.7,3597 C13.1@2749.7,3652
  Bottom Layer w10: v1(664.7,542) 705.7,542 ; P7.2@2740.23,3703.68 2740.23,3681.47 2749.7,3672 C13.1@2749.7,3652 ; v1(3381,1869) 4135.68,1869 v1(4136.84,1867.84)
  Bottom Layer w20: v1(693.7,830) 705.7,818 v1(705.7,689) 705.7,542 705.7,412 767.7,350 P13.1@795.7,350 ; v1(861.7,3629) 968.7,3629 1062.7,3535 1551.7,3535 v1(1589.7,3573) ; v1(1325.7,1001) 1370.7,1001 1453.7,1084 ; v1(1453.7,1221) 1453.7,1084 ; v1(1730.7,1216) 1730.7,1152 1662.7,1084 1453.7,1084
VCC-RTC: BT1.1 M1.106 | length 49.1
  Top Layer w10: v1(817.7,2617.78) v1@819.34,2616.14
  Top Layer w16: v1@819.34,2616.14 M1.106@866.14,2616.14
VCC-SYS: C10.1 C11.2 C19.1 D8.A L1.1 L2.1 M1.104 U1.3 U2.6 | length 7991.7
  Top Layer w12: L2.1@815.7,1381 815.7,1412 839.61,1435.91 880.61,1435.91 960.63,1515.93 M1.104@960.63,2675.39 ; v1(2999.7,3768) 3686,3081.7 3686,1740.7 3979.7,1447 D8.A@4156.47,1447
  Top Layer w16: U1.3@979.76,3718.13 U1.3@979.76,3718.13
  Top Layer w20: C10.1@1142.7,3613 v1(1142.7,3631) C11.2@1142.7,3649 1142.7,3708.7 U2.6@1142.51,3708.89 1232.29,3708.89 L1.1@1233.7,3710.3
  Top Layer w25: M1.104@960.63,2675.39 960.63,3058.07 796.7,3222 796.7,3542 950.7,3542 v1(979.7,3571)
  Top Layer w30: v1(979.7,3571) C19.1@979.7,3649 U1.3@979.76,3718.13
  Layer 1 w20: v1(979.7,3571) 1082.7,3571 v1(1142.7,3631)
  Bottom Layer w20: v1(1142.7,3631) 1142.7,3671 1384.7,3913 2854.7,3913 v1(2999.7,3768)
VCC_WIFI: C3.2 C4.2 R16.1 U3.9 | length 138.5
  Top Layer w16: R16.1@1017.7,3009.37 C3.2@1057.69,3009.37 C4.2@1057.69,3052.37 1057.92,3052.6 U3.9@1113.09,3052.6
VCCIO_WIFI: C5.2 M1.99 R5.1 R18.1 R20.1 R21.1 R22.1 R23.1 R24.1 U3.22 | length 690
  Top Layer w8: R18.1@1117.7,2846.37 1143.07,2821 ; M1.99@1127.95,2677.17 1127.95,2710.75 1136.7,2719.5 1136.7,2814.63 1143.07,2821 ; C5.2@1510.69,2882.37 1440.35,2882.4 R24.1@1404.32,2846.37 R23.1@1368.94,2846.37 1347.57,2825 1319.56,2825 R22.1@1298.19,2846.37 R21.1@1262.82,2846.37 R20.1@1227.44,2846.37 1195.07,2846.37 1169.7,2821 1143.07,2821
  Top Layer w12: C5.2@1510.69,2882.37 1547.33,2882.37 R5.1@1547.7,2882 ; C5.2@1510.69,2882.37 1510.72,2905 U3.22@1510.72,2938.43
VMID: C18.1 C20.2 M1.114 P1.1 P2.9 | length 4069.5
  Top Layer w10: v1@1934.51,3816.81 v1(1934.7,3817) ; C20.2@1934.7,3670 1934.7,3703.12 P2.9@1934.51,3703.31 1934.51,3730.81 v1(1934.7,3731)
  Top Layer w14: v1(866.14,2348.42) v1(903.12,2348.42)
  Top Layer w16: P1.1@454.98,2801.24 509.22,2747 C18.1@542.7,2747 v1(542.7,2466)
  Top Layer w20: P1.1@454.98,2801.24 272.22,2984 211.7,2984 161.7,3034 161.7,3602 357.7,3798 708.7,3798 779.7,3727 779.7,3628 829.7,3578 v1(911.7,3578)
  Layer 1 w20: v1(911.7,3578) 1036.7,3703 1222.7,3703 1358.7,3839 1912.7,3839 v1(1934.7,3817)
  Bottom Layer w14: v1(1934.7,3731) v1(1934.7,3817)
  Bottom Layer w16: v1@548.7,2466.53 548.7,2466 v1(542.7,2466) 660.28,2348.42 v1(866.14,2348.42) v1(903.12,2348.42)
VOL+: R32.2 R36.2 S6.2 | length 595.9
  Top Layer w8: R32.2@4171.7,3003 4171.7,3314 S6.2@4277.7,3420 4207.7,3490 R36.2@4207.7,3526
VOL-: R32.1 S2.2 | length 144.6
  Top Layer w8: R32.1@4207.7,3003 4207.7,2957.36 S2.2@4277.7,2887.36
WL-REG-ON: M1.61 R18.2 R19.2 U3.12 | length 1974.9
  Top Layer w5: v1(2077.66,2314.96) M1.61@2125.98,2314.96
  Top Layer w5.91: R18.2@1117.7,2882.37 R19.2@1156.69,2882.37 1156.39,2882.67 U3.12@1156.39,2938.43 1156.39,2970.69 1208.7,3023 v1(1226.7,3023)
  Bottom Layer w4: v1(1226.7,3023) 1226.7,2986 1240.7,2972 1282.7,2930 1282.7,2326 1479.7,2129 1948.7,2129 2055.7,2236 2055.7,2293 v1(2077.66,2314.96)
WL-WAKE-AP: M1.65 U3.13 | length 1369.8
  Top Layer w5: U3.13@1191.83,2938.43 1191.83,2972.13 1223.7,3004 v1(1297.7,3004) ; v1(2081.88,2466.82) 2099.88,2448.82 M1.65@2125.98,2448.82
  Bottom Layer w5: v1(1297.7,3004) 1351.7,2950 1351.7,2679 1460.7,2570 1977.7,2570 2080.88,2466.82 v1(2081.88,2466.82)
pads on no net: BT1.0 Designator53.0 Designator54.0 Designator55.0 Designator56.0 Designator57.0 Designator58.0 J1.A8 J1.B8 P1.7 P6.37 P6.38 P6.39 P6.40 P9.4 P9.9 P9.G P11.1 P11.5 P12.2 U3.4 U3.5 U3.8 U3.10 U3.11 U3.21 U3.23 U3.25 U3.26 U3.27 U3.28 U3.29 U3.30 U3.32 U3.35 U3.37 U3.38 U3.39 U3.40 U7.1 U8.2 U8.10 U8.11 U8.12

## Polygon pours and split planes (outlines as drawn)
GND on Top Layer "GND_L01_P000" (solid, remove dead copper, pour order 0): -1.3,2.5 4329.41,2.5 4329.41,3939.5 -1.3,3939.5
GND on Bottom Layer "GND_L04_P001" (solid, remove dead copper, pour order 1): 2.7,6.5 4333.41,6.5 4333.41,3943.5 2.7,3943.5
GND on Layer 1 "GND_L03_P002" (solid, remove dead copper, pour order 2): -0.3,-2.5 4330.41,-2.5 4330.41,3934.5 -0.3,3934.5
GND on Layer 2 (split plane): 4320.62,3937.01 4320.62,0 4320.62,-186.76 10.09,-186.76 10.09,0 10.09,3937.01 10.09,4123.77 4320.62,4123.77

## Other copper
Top Layer:
  region net VCC3V3: 1671.7,1242.37
  region net VCC3V3: 1671.7,1242.37
  region net VCC3V3: 1671.7,1242.37
  region net VCC3V3: 1671.7,1242.37
  region net VCC3V3: 1671.7,1242.37
  region net VCC3V3: 1671.7,1242.37

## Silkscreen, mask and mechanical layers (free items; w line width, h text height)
Top Overlay:
  lines w6: 2350.71,3938.07 2350.71,965.63 4063.31,965.63 4063.31,3938.07 2351.77,3938.07
  lines w10: 62.92,2251.2 ccw(c259.77,2251.2) 456.62,2251.2 456.62,2448.06 ccw(c259.77,2448.06) 62.92,2448.06 62.92,2251.2
  text "已重新铺铜" at 1785.42,3992.64 h140
  text "DSI+CTP" at 1379.24,3765.63 h78.74
  text "BOOT" at 89.46,3593.62 h60
  text "TYPEC" at 607.7,3559.82 h78.74
  text "RST" at 111.97,3379.62 h60
  text "MIPI-DSI" at 1855.7,3339.82 h78.74
  text "VOL+" at 4102.75,3304.15 h80
  text "ANT" at 611.7,3274 h80
  text "_" at 134.7,3188.96 h100 r180
  text "TS" at 177.7,3178.62 h60
  text "+" at 339.04,3176.71 h100 r90
  text "R" at 2218.31,3115.8 h78.74
  text "BAT" at 359.7,3088.8 h78.74
  text "T" at 2218.31,3014.18 h78.74
  text "G" at 2218.31,2916 h78.74
  text "VOL-" at 4110.85,2767.89 h80
  text "PWR" at 4112.83,2230.05 h80
  text "SPEAKER" at 95.59,1981.82 h78.74
  text "LED" at 4128.44,1756 h80
  text "OV8858 / GC2385" at 83.7,1652.87 h78.74
  text "OV2680" at 103.09,1360.79 h78.74
  text "RGB" at 4120.7,1247.83 h80
  text "MIPI-CSI" at 63.42,1093.23 h78.74
  text "3.1inch IPS LCD" at 2748.7,1006.67 h150
  text "M-Core TEST" at 1177,940.46 h140
  text "MIC-M" at 2149.7,787.82 h78.74
  text "MIC-H" at 4126.7,787.82 h78.74
  text "V1.1-20230511" at 1184.07,776.11 h100
  text "PB8" at 820.08,528 h60 r90
  text "PB6" at 919.67,528.04 h60 r90
  text "PB4" at 1018.52,528.1 h60 r90
  text "PH5" at 1117.98,526.42 h60 r90
  text "PH7" at 1216.83,526.56 h60 r90
  text "PH9" at 1316.42,526.52 h60 r90
  text "RX2" at 1713.59,526.79 h60 r90
  text "GND" at 2116.08,517 h60 r90
  text "PH11" at 1415.39,515.35 h60 r90
  text "PB3" at 1813.69,513.86 h60 r90
  text "PE6" at 2012.86,513.41 h60 r90
  text "PH13" at 1515.03,511.65 h60 r90
  text "PH18" at 1614.62,511.61 h60 r90
  text "PL10" at 1913.95,510.15 h60 r90
  text "TF CARD" at 87.7,286.82 h78.74
  text "HP" at 2113.03,194.44 h60 r90
  text "3V3" at 813.03,183 h60 r90
  text "PB7" at 912.58,180.96 h60 r90
  text "PB5" at 1012.74,180.82 h60 r90
  text "TX2" at 1712.16,181.23 h60 r90
  text "PH4" at 1112.28,179.55 h60 r90
  text "PH6" at 1212.58,179.48 h60 r90
  text "PH8" at 1312.87,179.44 h60 r90
  text "PL11" at 2013.49,172.72 h60 r90
  text "PH10" at 1413.16,164.63 h60 r90
  text "PH12" at 1512.82,164.76 h60 r90
  text "PH17" at 1612.49,164.57 h60 r90
  text "PB2" at 1813.61,163.14 h60 r90
  text "PL9" at 1913.82,163.26 h60 r90
Bottom Overlay:
  text "CTP" at 2956.7,3763.82 h78.74
  text "RGB" at 2492.7,3757.82 h78.74
Top Solder:
  circle w62.99: c137.79,3799.21 r82.68
  circle w62.99: c4192.91,137.8 r82.68
  circle w62.99: c4192.91,3799.21 r82.68
  circle w62.99: c137.79,137.8 r82.68
Bottom Solder:
  circle w62.99: c137.79,3799.21 r82.68
  circle w62.99: c137.79,137.8 r82.68
  circle w62.99: c4192.91,137.8 r82.68
  circle w62.99: c4192.91,3799.21 r82.68
Mechanical 1:
  circle w5: c137.79,3799.21 r54.13
  circle w5: c4192.91,3799.21 r54.13
  circle w5: c4192.91,137.8 r54.13
  circle w5: c137.79,137.8 r54.13
  lines w3.94: 0,0 0,-196.85 4330.71,-196.85 4330.71,0 ; 0,0 0,3937.01 ; 0,0 4330.71,0 ; 0,3937.01 0,4133.86 4330.71,4133.86 4330.71,3937.01 ; 0,3937.01 4330.71,3937.01 ; 4330.71,0 4330.71,3937.01
  lines w10: 143.16,2249.22 ccw(c261.27,2249.22) 379.38,2249.22 379.38,2446.08 ccw(c261.27,2446.08) 143.16,2446.08 143.16,2249.22

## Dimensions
4063.31,965.63 to 3623.71,80.63 on Mechanical 2
4063.31,965.63 to 3581.71,22.63 on Mechanical 2
2350.71,965.63 to 2533.71,180.63 on Mechanical 2
2350.71,965.63 to 2489.71,190.63 on Mechanical 2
